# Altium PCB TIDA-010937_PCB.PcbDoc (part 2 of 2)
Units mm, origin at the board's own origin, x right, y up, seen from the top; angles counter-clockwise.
Board outline 43.5 x 86.34 mm, 4 copper layers (Top Layer, GND, PWR, Bottom Layer), stack 1.856 mm thick; 90 components, 44 nets, 203 pads, 101 vias.
Unrouted connection lines stored in the file: 1.
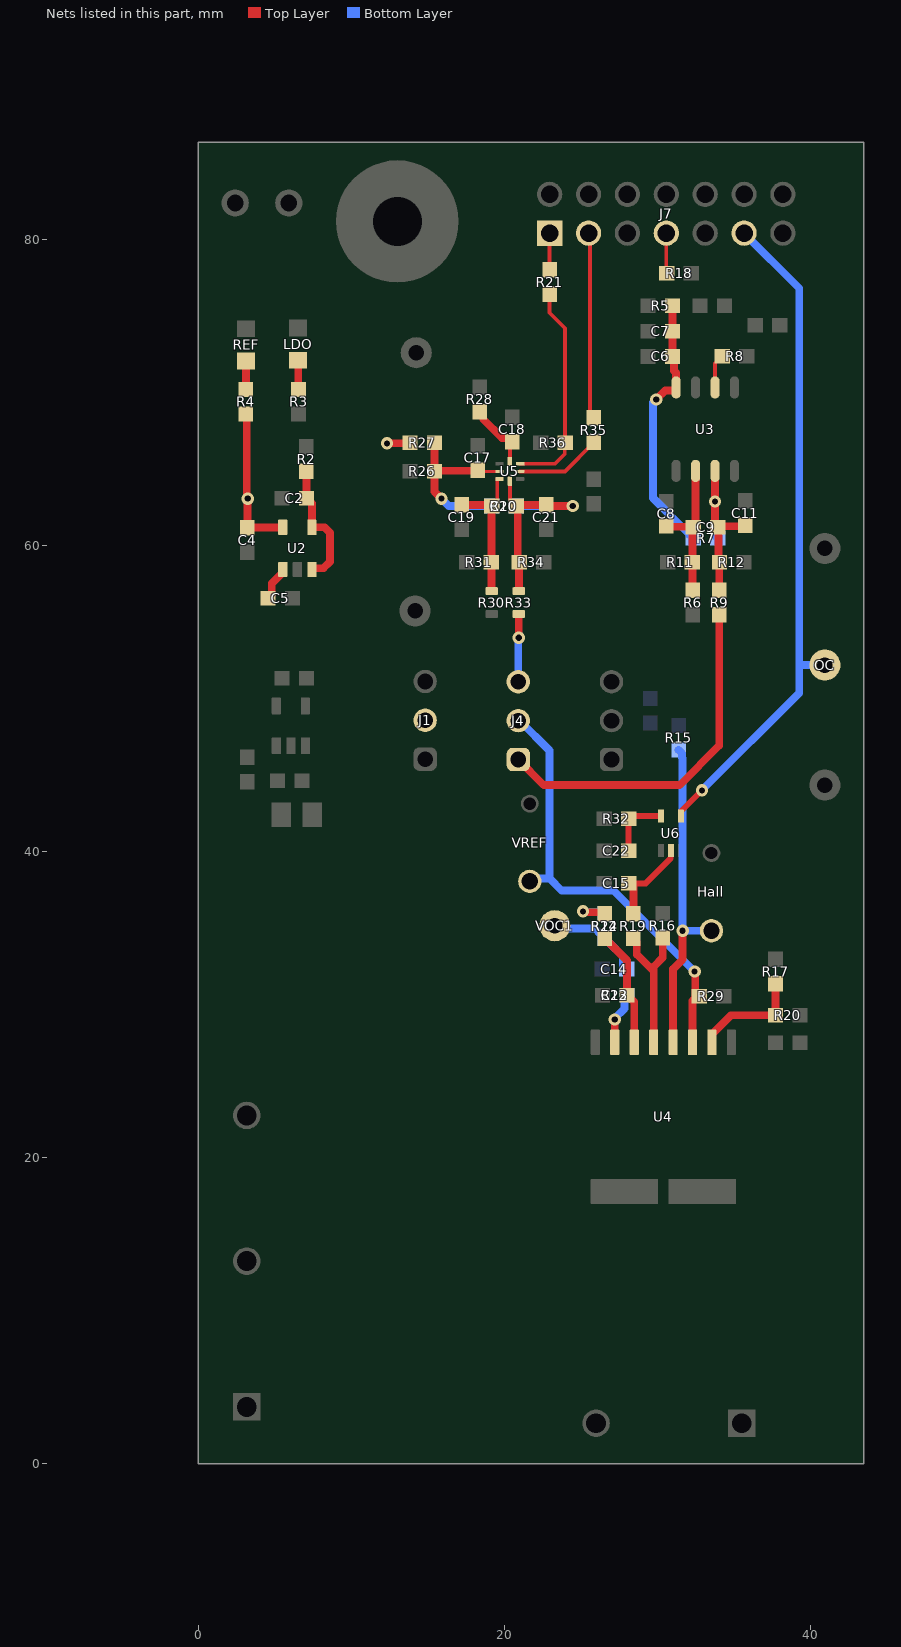
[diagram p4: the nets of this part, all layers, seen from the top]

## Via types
v1: diameter 0.8, hole 0.4, Top Layer to Bottom Layer, 101 vias

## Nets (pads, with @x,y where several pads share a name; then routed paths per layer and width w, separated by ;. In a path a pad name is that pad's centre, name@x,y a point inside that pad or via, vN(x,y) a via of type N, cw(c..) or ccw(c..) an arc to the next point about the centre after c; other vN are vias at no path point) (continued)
NetC2_1: C2.1 R2.2 U2.3 U2.4 | length 8.1
  Top Layer w0.508: C2.1@7.076,63.089 R2.2@7.076,64.836 ; C2.1@7.322,62.843 7.431,62.734 U2.4@7.431,61.177 8.258,61.177 8.614,60.82 8.614,58.934 8.185,58.505 7.477,58.505 7.431,58.459 U2.3@7.431,58.427
NetC8_2: C8.2 C9.1 R6.2 R11.2 U3.2 | length 9.4
  Top Layer w0.508: C8.2@30.572,61.26 30.612,61.22 32.191,61.22 C9.1@32.358,61.053 ; R6.2@32.319,57.064 32.302,57.08 32.302,58.874 R11.2@32.286,58.89 32.305,58.909 32.305,61.07 C9.1@32.324,61.089 ; C9.1@32.5,61.424 U3.2@32.5,64.864
NetC9_2: C9.2 C11.1 R7.1 R9.2 R12.2 U3.3 | length 12.1
  Top Layer w0.508: U3.3@33.77,64.864 v1(33.77,62.86) 33.77,61.368 C9.2@33.958,61.18 ; C9.2@33.924,61.089 33.991,61.021 33.991,58.958 R12.2@34.059,58.89 34.054,58.885 34.054,57.069 R9.2@34.049,57.064 ; C9.2@34.02,61.242 35.689,61.242 C11.1@35.751,61.304
  Bottom Layer w0.508: v1(33.77,62.86) 33.77,60.643 R7.1@33.958,60.455
NetC12_1: C12.1 R14.1 U4.8 | length 7.6
  Top Layer w0.508: R14.1@26.567,34.33 26.567,34.305 26.788,34.084 26.813,34.084 28.021,32.875 C12.1@28.021,30.606 28.046,30.606 28.491,30.161 U4.8@28.491,27.534
NetC15_1: C15.1 R19.2 U6.2 | length 6.1
  Top Layer w0.381: C15.1@28.124,37.918 28.149,37.918 29.245,37.918 30.882,39.555 30.882,40.053 U6.2@30.891,40.062
  Top Layer w0.508: C15.1@28.149,37.918 28.439,37.629 R19.2@28.439,35.93
NetC18_2: C18.2 R28.1 U5.4 | length 4.4
  Top Layer w0.254: U5.4@20.365,65.484 20.365,66.587 C18.2@20.524,66.745
  Top Layer w0.508: R28.1@18.413,68.737 18.634,68.516 18.634,68.241 19.859,67.016 20.303,67.016 20.37,66.95 C18.2@20.37,66.78
NetC19_2: C19.2 C20.1 R30.1 R31.2 U5.7 | length 9.6
  Top Layer w0.254: C20.1@19.183,62.57 19.208,62.57 19.232,62.594 19.542,62.904 19.542,64.332 19.544,64.334 U5.7@19.69,64.334
  Top Layer w0.508: C19.2@17.274,62.68 17.311,62.642 19.184,62.642 19.222,62.605 19.232,62.594 C20.1@19.256,62.57 ; R30.1@19.179,57.064 19.164,57.079 19.164,58.873 R31.2@19.148,58.889 19.166,58.906 19.166,62.552 C20.1@19.183,62.57 ; R31.2@19.265,58.908 R31.2@19.268,58.905
NetC20_2: C20.2 C21.1 R10.1 R33.1 R34.2 U5.8 | length 15.2
  Top Layer w0.254: U5.8@20.365,64.184 20.365,62.963 20.686,62.642 C20.2@20.859,62.642
  Top Layer w0.508: R33.1@20.948,57.064 20.964,57.08 20.964,58.874 R34.2@20.98,58.89 20.882,58.989 R34.2@20.882,59.107 ; R34.2@21.1,58.907 21.083,58.907 R34.2@20.882,59.107 ; C21.1@22.752,62.645 C21.1@22.754,62.643 ; v1(24.478,62.57) 22.827,62.57 C21.1@22.754,62.643 ; R34.2@20.882,59.107 20.882,62.545 20.822,62.605 20.859,62.642 22.753,62.642 C21.1@22.754,62.643
  Bottom Layer w0.508: R10.1@20.783,62.57 v1(24.478,62.57)
NetC22_1: C22.1 R32.1 U6.5 | length 4.3
  Top Layer w0.381: C22.1@28.124,40.044 R32.1@28.124,42.14 28.296,42.312 U6.5@30.241,42.312
NetJ7_1: J7.1 R21.2 | length 2.6
  Top Layer w0.254: R21.2@22.968,77.788 J7.1@22.968,80.405
NetJ7_7: J7.7 R18.2 | length 2.6
  Top Layer w0.254: J7.7@30.588,80.397 30.588,77.812 R18.2@30.62,77.779
NetLDO_2: LDO.2 R3.1 | length 2
  Top Layer w0.508: LDO.2@6.527,72.095 6.543,72.079 6.543,70.242 6.601,70.184 R3.1@6.601,70.209
NetR4_1: R4.1 REF.2 | length 1.9
  Top Layer w0.508: R4.1@3.11,70.184 3.12,70.194 3.12,72.044 REF.2@3.131,72.054
NetR8_1: R8.1 U3.6 | length 2.2
  Top Layer w0.254: U3.6@33.77,70.314 33.77,71.9 34.221,72.35 R8.1@34.246,72.35
NetR16_1: R16.1 R19.1 U4.7 | length 9.8
  Top Layer w0.508: R19.1@28.439,34.33 28.66,34.109 28.66,33.274 29.761,32.172 ; U4.7@29.761,27.534 29.761,32.172 ; R16.1@30.354,34.348 30.354,33.069 29.761,32.476 29.761,32.172
NetR17_1: R17.1 R20.1 U4.4 | length 7.2
  Top Layer w0.508: U4.4@33.571,27.534 33.571,28.059 34.819,29.306 R20.1@37.723,29.306 R17.1@37.723,31.356
NetR35_2: R35.2 U5.2 | length 5.6
  Top Layer w0.254: U5.2@21.04,64.834 23.969,64.834 25.84,66.705 R35.2@25.84,66.73
OC_Blank: J7.11 OC.1 U6.4 | length 44.5
  Top Layer w0.381: U6.4@31.541,42.312 31.551,42.322 31.551,42.629 v1(32.915,43.993)
  Bottom Layer w0.508: v1(32.915,43.993) 39.273,50.351 39.273,52.18 ; J7.11@35.668,80.397 39.273,76.792 39.273,52.18 ; OC.1@40.947,52.18 39.273,52.18
REF_ADS: J4.3 R33.2 | length 4.4
  Top Layer w0.508: v1(20.948,53.96) R33.2@20.948,55.439
  Bottom Layer w0.508: J4.3@20.919,51.09 20.919,53.93 v1(20.948,53.96)
REF_AMC: J4.1 R9.1 | length 23.4
  Top Layer w0.508: J4.1@20.919,46.01 22.591,44.338 31.458,44.338 34.049,46.929 R9.1@34.049,55.464
SCLK: R21.1 R36.2 U5.3 | length 14.1
  Top Layer w0.254: U5.3@21.04,65.334 23.308,65.334 23.956,65.982 23.956,66.341 24.304,66.689 R36.2@24.316,66.689 ; R21.1@22.968,76.322 22.968,75.193 23.977,74.184 R36.2@23.977,66.689
SDO: J7.3 R35.1 | length 12.6
  Top Layer w0.254: J7.3@24.963,80.564 25.601,79.925 25.601,68.568 R35.1@25.84,68.33
V_Hall: J1.2 R14.2 R22.1 | length 3
  Top Layer w0.508: v1(25.146,36.089) 25.202,36.033 26.463,36.033 R14.2@26.567,35.93
  Bottom Layer w0.508: v1(25.146,36.089) 25.202,36.033 26.463,36.033 R22.1@26.567,35.93
VBIAS: C5.1 U2.1 | length 2.3
  Top Layer w0.508: C5.1@4.563,56.529 4.588,56.529 4.809,56.75 4.809,57.504 5.531,58.227 U2.1@5.531,58.427
VDD_ADS: C17.2 R10.2 R26.2 R27.2 U5.6 | length 11.4
  Top Layer w0.152: C17.2@18.243,64.871 C17.2@18.28,64.834
  Top Layer w0.2: C17.2@18.28,64.834 U5.6@19.69,64.834
  Top Layer w0.508: R27.2@15.476,66.546 15.439,66.509 R26.2@15.439,64.845 15.439,63.512 v1(15.899,63.052) ; R26.2@15.514,64.871 C17.2@18.243,64.871
  Bottom Layer w0.508: v1(15.899,63.052) 16.381,62.57 R10.2@19.183,62.57
VDD_AMC: C6.2 C7.1 R5.2 R7.2 U3.8 | length 17.4
  Top Layer w0.508: v1(29.93,69.537) 30.513,70.121 31.188,70.121 31.213,70.146 U3.8@31.213,70.314 ; R5.2@30.993,75.655 C7.1@30.993,73.992 C6.2@30.993,72.339 31.096,72.236 31.096,71.406 31.23,71.272 U3.8@31.23,70.314
  Bottom Layer w0.508: v1(29.93,69.537) 29.718,69.325 29.718,63.096 32.112,60.701 32.112,60.676 32.333,60.455 R7.2@32.358,60.455
VOC1: C14.1 R22.2 R23.1 U4.9 VOC1.1 | length 11.1
  Top Layer w0.508: U4.9@27.175,27.58 U4.9@27.221,27.534 v1(27.221,29.021)
  Bottom Layer w0.508: VOC1.1@23.304,35.148 23.476,34.976 25.921,34.976 26.321,34.576 26.346,34.576 26.567,34.355 R22.2@26.567,34.33 ; R22.2@26.813,34.084 27.768,33.129 27.768,32.541 27.989,32.32 C14.1@27.996,32.32 ; v1(27.221,29.021) 27.221,29.1 27.856,29.735 27.856,30.44 R23.1@28.021,30.606 C14.1@28.021,32.32
Vout: Hall.1 R15.1 U4.6 | length 21.3
  Top Layer w0.508: U4.6@31.031,27.534 31.031,32.32 31.654,32.944 v1(31.654,34.819)
  Bottom Layer w0.508: R15.1@31.391,46.627 31.612,46.406 31.612,46.126 31.654,46.084 v1(31.654,34.819) Hall.1@33.539,34.819
VREF: J4.2 R29.2 U4.5 VREF.1 | length 29.3
  Top Layer w0.508: U4.5@32.301,27.534 32.301,30.237 R29.2@32.522,30.458 ; v1(32.44,32.151) 32.482,32.109 32.482,30.549 R29.2@32.524,30.507
  Bottom Layer w0.508: J4.2@20.919,48.55 21.006,48.55 22.957,46.6 22.957,38.24 ; VREF.1@21.673,38.045 21.867,38.24 22.957,38.24 ; v1(32.44,32.151) 27.148,37.443 23.753,37.443 22.957,38.24
VREF_3V3: C4.1 R4.2 R27.1 U2.5 | length 11.3
  Top Layer w0.508: R4.2@3.11,68.584 3.183,68.511 3.183,63.108 v1(3.239,63.052) 3.231,63.044 C4.1@3.231,61.153 ; C4.1@3.223,61.145 C4.1@3.231,61.153 ; U2.5@5.531,61.177 5.516,61.161 3.239,61.161 C4.1@3.231,61.153 ; v1@12.349,66.678 13.827,66.678 R27.1@13.839,66.689 R27.1@13.811,66.717
  other v1: 12.337,66.666
pads on no net: H1.1 J5.2 LBL1.0 U1.4 U3.4 U4.10 U6.1

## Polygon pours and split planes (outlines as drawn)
IN- on PWR "PWR_IN-_P060" (solid, pour order 60): 37.902,16.967 37.902,1.651 30.72,1.651 30.72,16.967
IN+ on PWR "PWR_IN+_P057" (solid, remove dead copper, pour order 57): 30.063,16.967 30.063,1.651 22.882,1.651 22.882,16.967
+5V on PWR "PWR_+5V_P043" (solid, remove dead copper, pour order 43): 0,86.341 11.328,86.341 11.328,33.399 9.026,33.392 0,33.392
V_Hall on PWR "PWR_V_HALL_P042" (solid, remove dead copper, pour order 42): 11.34,50.091 18.587,50.091 18.587,47.098 34.004,31.681 43.5,31.681 43.5,26.459 43.456,26.415 43.412,26.459 25.202,26.459 25.202,33.392 11.243,33.392
LDO_3V3 on PWR "PWR_LDO_3V3_P045" (solid, remove dead copper, pour order 45): 11.34,50.091 11.328,50.103 11.328,86.341 43.5,86.341 43.5,31.681 34.004,31.681 18.587,47.098 18.587,50.091
+5V on PWR "PWR_+5V_P044" (solid, remove dead copper, pour order 44): 10.847,46.874 16.022,46.874 16.1,46.797 16.1,44.979 10.897,44.979 10.847,45.028
GND on Top Layer "TOP_LAYER_GND_P047" (solid, remove dead copper, pour order 47): 0,86.341 43.5,86.341 43.5,26.459 25.202,26.459 25.202,33.392 0,33.392
IN- on Top Layer "TOP_LAYER_IN-_P020" (solid, pour order 20): 37.902,18.603 37.902,1.651 30.72,1.651 30.72,18.603
IN1 on Top Layer "TOP_LAYER_IN1_P055" (solid, pour order 55): 0,25.654 10.636,25.654 10.795,25.495 10.795,20.211 0.051,20.211 0,20.262
IN1 on Top Layer "TOP_LAYER_IN1_P054" (solid, pour order 54): 0,7.043 10.636,7.043 10.795,6.883 10.795,1.6 0.051,1.6 0,1.651
IN1 on Top Layer "TOP_LAYER_IN1_P053" (solid, pour order 53): 9.722,1.651 17.78,1.651 17.813,22.659 14.975,25.654 9.715,25.654
IN+ on Top Layer "TOP_LAYER_IN+_P016" (solid, remove dead copper, pour order 16): 30.063,18.603 30.063,1.651 22.882,1.651 22.882,18.603
LDO_3V3 on Top Layer "TOP_LAYER_LDO_3V3_P031" (solid, remove dead copper, pour order 31): 4.92,50.833 7.836,50.833 7.836,54.831 7.733,54.934 4.889,54.934 4.762,54.807 4.762,51.107
IN- on Bottom Layer "BOTTOM_LAYER_IN-_P061" (solid, pour order 61): 37.902,16.967 37.902,1.651 30.72,1.651 30.72,16.967
IN+ on Bottom Layer "BOTTOM_LAYER_IN+_P058" (solid, remove dead copper, pour order 58): 30.063,16.967 30.063,1.651 22.882,1.651 22.882,16.967
LDO_3V3 on Bottom Layer "BOTTOM_LAYER_LDO_3V3_P030" (solid, remove dead copper, pour order 30): 4.762,54.807 4.889,54.934 10.979,54.934 10.979,57.45 16.798,57.45 16.798,50.182 16.713,50.096 4.982,50.096 4.762,50.316
VREF_3V3 on Bottom Layer "BOTTOM_LAYER_VREF_3V3_P006" (solid, remove dead copper, pour order 6): 2.379,67.463 2.379,60.295 14.471,60.295 14.471,67.463
IN- on GND "GND_IN-_P059" (solid, pour order 59): 37.902,16.967 37.902,1.651 30.72,1.651 30.72,16.967
IN+ on GND "GND_IN+_P056" (solid, remove dead copper, pour order 56): 30.063,16.967 30.063,1.651 22.882,1.651 22.882,16.967
GND on GND "GND_GND_P046" (solid, pour order 46): 0,86.341 43.5,86.341 43.5,26.547 43.412,26.459 25.202,26.459 25.202,33.392 0,33.392

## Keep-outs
Keep-Out Layer:
  text ".Layer_Name" at 14.656,-21.806 h1.02

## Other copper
Top Layer:
  pour cut-out: 37.902,16.967 35.136,16.967 35.136,18.603 37.902,18.603
  pour cut-out: 25.647,16.967 22.882,16.967 22.882,18.603 25.647,18.603
  text ".Layer_Name" at 14.656,-21.806 h1.02
GND:
  pour cut-out: 37.902,16.967 35.136,16.967 35.136,18.603 37.902,18.603
  pour cut-out: 25.647,16.967 22.882,16.967 22.882,18.603 25.647,18.603
PWR:
  pour cut-out: 37.902,16.967 35.136,16.967 35.136,18.603 37.902,18.603
  pour cut-out: 25.647,16.967 22.882,16.967 22.882,18.603 25.647,18.603
Bottom Layer:
  pour cut-out: 37.902,16.967 35.136,16.967 35.136,18.603 37.902,18.603
  pour cut-out: 25.647,16.967 22.882,16.967 22.882,18.603 25.647,18.603
  text ".Layer_Name" at 14.656,-21.806 h1.02

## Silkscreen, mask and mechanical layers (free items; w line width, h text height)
Top Overlay:
  lines w0.508: 0.449,33.392 25.202,33.392 25.202,26.455 43.456,26.415
  text "+5V" at 0.676,76.842 h1.02
  text "GND" at 5.111,76.842 h1.02
  text "1:SCLK / 3:SDO / 5:CS / 7:CLK / 9:DOUT / 11:OC / 13:FAULT" at 37.791,65.156 h1.02
  text "3V3" at 16.475,50.775 h1.02
  text "ADS" at 23.093,50.786 h1.02
  text "5V" at 16.493,45.627 h1.02
  text "AMC" at 23.023,45.602 h1.02
  text "TIDA-010937-E1" at 3.113,29.905 h2.54
  text "850V  / MAX" at 18.432,20.211 h1.52
  text "66A  / MAX" at 38.156,20.218 h1.52
  text ".Layer_Name" at 14.656,-21.806 h1.02
Bottom Overlay:
  text "IN+" at 22.034,11.182 h1.52 r180
  text "IN-" at 42.599,11.182 h1.52 r180
  text ".Layer_Name" at 14.656,-21.806 h1.02
Top Paste:
  text ".Layer_Name" at 14.656,-21.806 h1.02
Bottom Paste:
  text ".Layer_Name" at 14.656,-21.806 h1.02
Top Solder:
  text ".Layer_Name" at 14.656,-21.806 h1.02
  text ".Layer_Name" at 14.656,-21.806 h1.02
Bottom Solder:
  text ".Layer_Name" at 14.656,-21.806 h1.02
Drill Guide:
  text ".Layer_Name" at 14.656,-21.806 h1.02
M1 Board Outline:
  the board outline again, w0.254
  text ".Layer_Name" at 14.656,-21.806 h1.02
M2 Board Dimensions:
  rectangle: 0,-6.985 3.175,-3.81
  rectangle: 3.175,-10.16 12.7,-6.985
  lines w0.178: 0,-6.985 25.4,-6.985 ; 3.175,-10.16 3.175,-3.81 ; 6.35,-10.16 6.35,-3.81 ; 12.7,-10.16 12.7,-3.81 ; 19.05,-10.16 19.05,-3.81 ; 0,-10.16 25.4,-10.16 25.4,-3.81 0,-3.81 0,-10.16
  text ".Layer_Name" at 14.656,-21.806 h1.02
M3 3D STEP Top:
  text ".Layer_Name" at 14.656,-21.806 h1.02
M4 3D STEP Bottom:
  text ".Layer_Name" at 14.656,-21.806 h1.02
M5 Assembly Top:
  lines w0.254: -7.417,-23.626 160.223,-23.626 ; -7.417,-18.462 160.274,-18.462 ; -7.417,-13.297 -7.417,-28.791 94.31,-28.791 160.274,-28.791 160.274,-13.297 -7.404,-13.297 -7.404,-28.791 32.614,-28.791 ; 55.194,-28.791 55.194,-13.297 ; 87.376,-18.462 87.376,-13.297 ; 108.712,-18.462 108.712,-13.297 ; 124.511,-28.956 124.511,-23.804
  text "COMPONENTS MARKED 'DNP' SHOULD NOT BE POPULATED." at 29.299,-8.09 h1.02
  text "ASSEMBLY VARIANT:" at 29.286,-11.024 h1.02
  text ".VariantName" at 55.601,-11.024 h1.02
  text "PCB VIEWED FROM TOP SIDE" at -5.804,-16.654 h1.02
  text "BOARD #:" at 57.099,-16.654 h1.02
  text ".PRJ_Number" at 70.955,-16.654 h1.02
  text "REV:" at 92.405,-16.654 h1.02
  text ".PCB_Rev" at 99.809,-16.654 h1.02
  text "SVN REV:" at 113.69,-16.654 h1.02
  text ".VersionControl_RevNumber" at 126.543,-16.654 h1.02
  text "TID #:" at 57.099,-21.819 h1.02
  text ".TID" at 70.955,-21.819 h1.02
  text "PLOT NAME =" at -5.804,-27.034 h1.02
  text ".plot_File_Name" at 14.656,-27.034 h1.02
  text "GENERATED    :" at 57.15,-27.034 h1.02
  text ".Print_Date" at 79.235,-27.034 h1.02
  text ".Print_Time" at 97.752,-27.034 h1.02
  text "TEXAS INSTRUMENTS" at 129.87,-27.034 h1.02
M6 Assembly Bottom:
  lines w0.254: -7.429,-18.474 160.261,-18.474 ; -7.379,-23.639 160.261,-23.639 ; 28.334,-28.969 28.334,-23.817 ; 44.133,-18.474 44.133,-13.31 ; 65.468,-18.474 65.468,-13.31 ; 97.65,-28.804 97.65,-13.31 ; 120.231,-28.804 160.249,-28.804 160.249,-13.31 -7.429,-13.31 -7.429,-28.804 58.534,-28.804 160.261,-28.804 160.261,-13.31
  text "COMPONENTS MARKED 'DNP' SHOULD NOT BE POPULATED." at 154.991,-8.077 h1.02
  text ".VariantName" at 128.473,-11.024 h1.02
  text "ASSEMBLY VARIANT:" at 154.864,-11.024 h1.02
  text ".VersionControl_RevNumber" at 26.302,-16.667 h1.02
  text "SVN REV:" at 39.154,-16.667 h1.02
  text ".PCB_Rev" at 53.035,-16.667 h1.02
  text "REV:" at 60.439,-16.667 h1.02
  text ".PRJ_Number" at 81.89,-16.667 h1.02
  text "BOARD #:" at 95.745,-16.667 h1.02
  text "PCB VIEWED FROM BOTTOM SIDE" at 158.648,-16.667 h1.02
  text ".TID" at 81.89,-21.831 h1.02
  text "TID #:" at 95.745,-21.831 h1.02
  text "TEXAS INSTRUMENTS" at 22.974,-27.047 h1.02
  text ".Print_Time" at 55.093,-27.047 h1.02
  text ".Print_Date" at 73.609,-27.047 h1.02
  text "GENERATED    :" at 95.694,-27.047 h1.02
  text ".plot_File_Name" at 138.189,-27.047 h1.02
  text "PLOT NAME =" at 158.648,-27.047 h1.02
M9 Title Sheet:
  drawing of 57 lines, arcs and shapes, not listed
  text "1" at 18.792,204.127 h1.78
  text "2" at 82.182,204.127 h1.78
  text "3" at 145.411,204.127 h1.78
  text "4" at 209.08,204.127 h1.78
  text "5" at 272.555,204.127 h1.78
  text "6" at 336.182,204.127 h1.78
  text "A" at -10.579,175.095 h1.78
  text "A" at 365.341,175.095 h1.78
  text "B" at -10.579,114.643 h1.78
  text "B" at 365.341,114.643 h1.78
  text "C" at -10.579,54.318 h1.78
  text "C" at 365.341,54.318 h1.78
  text "PROJECT TITLE:" at 288.125,7.048 h1.14
  text ".PRJ_Title" at 289.395,3.662 h1.78
  text "DESIGNED FOR:" at 288.125,-0.597 h1.14
  text ".PRJ_Customer" at 289.395,-4.153 h1.78
  text "D" at -10.579,-5.88 h1.78
  text "D" at 365.341,-5.88 h1.78
  text "FILE NAME:" at 288.125,-8.217 h1.14
  text ".PCB_File_Name_No_Path" at 289.395,-11.265 h1.78
  text "Texas Instruments (TI) and/or its licensors do not warrant the accuracy or completeness of this specification" at 161.9,-15.376 h1.14
  text "ENGINEER:" at 288.125,-15.583 h1.14
  text "LAYOUT BY:" at 326.352,-15.583 h1.14
  text "or any information contained therein. TI and/or its licensors do not warrant that this design will meet" at 160.757,-18.237 h1.14
  text ".PRJ_Engineer" at 289.395,-19.52 h1.78
  text ".PCB_Layout" at 327.635,-19.52 h1.78
  text "the specifications, will be suitable for your application or fit for any particular purpose, or will operate in" at 160.757,-21.099 h1.14
  text ".Layer_Name" at 14.656,-21.806 h1.02
  text "ALTIUM DESIGNER VERSION:" at 326.352,-23.457 h1.14
  text "an implementation. TI and/or its licensors do not warrant that the design is production worthy. You should" at 160.757,-23.961 h1.14
  text "completely validate and test your design implementation to confirm the system functionality for your application." at 161.9,-26.822 h1.14
  text ".print_Scale" at 289.395,-26.843 h1.78
  text ".Application_BuildNumber" at 327.635,-26.843 h1.78
  text "1" at 18.792,-32.093 h1.78
  text "2" at 82.182,-32.093 h1.78
  text "3" at 145.411,-32.093 h1.78
  text "4" at 209.08,-32.093 h1.78
  text "5" at 272.555,-32.093 h1.78
  text "6" at 336.182,-32.093 h1.78
M10 Fab Notes:
  drawing of 189 lines, arcs and shapes, not listed
  text "DESIGN INFORMATION" at 314.503,161.447 h1.02
  text "MIN. TRACK WIDTH:" at 298.131,158.091 h1.02
  text "8" at 325.976,158.091 h1.02
  text "MIL" at 329.907,158.091 h1.02
  text "7.874" at 321.75,155 h1.02
  text "MIN. CLEARANCE:" at 298.131,154.938 h1.02
  text "MIL" at 329.907,154.938 h1.02
  text "MIN. VIA PAD SIZE:" at 298.131,151.785 h1.02
  text "24" at 325.214,151.785 h1.02
  text "MIL" at 329.907,151.785 h1.02
  text "0.05mm (2MIL)" at 315.784,148.486 h1.02
  text "MINIMUM ANNULAR RING" at 289.769,148.277 h1.02
  text "EXTERNAL" at 333.768,148.277 h1.02
  text "PER" at 294.849,145.48 h1.02
  text "IPC-D-275 CLASS 2 LEVEL C" at 300.437,145.48 h1.02
  text "MIL, HOLES" at 338.238,142.928 h1.02
  text "+/-" at 328.27,142.709 h1.02
  text "+/-" at 349.961,142.709 h1.02
  text "REGISTRATION TOLERANCES:" at 289.769,142.682 h1.02
  text "METAL" at 320.243,142.682 h1.02
  text "5" at 334.879,142.683 h1.02
  text "3" at 356.037,142.683 h1.02
  text "MIL" at 358.99,142.682 h1.02
  text "HOLE SIZE TOLERANCE (UNLESS OTHERWISE SPECIFIED):" at 289.769,140.185 h1.02
  text "+/-" at 349.961,140.112 h1.02
  text "3" at 356.037,140.085 h1.02
  text "MIL" at 358.99,140.085 h1.02
  text "MATERIAL:" at 287.87,136.589 h1.02
  text "FR-4 High Tg" at 312.926,133.324 h1.02
  text "X" at 309.257,133.122 h1.02
  text "FR-4" at 298.563,133.007 h1.02
  text "OTHER" at 336.358,133.007 h1.02
  text "62 MIL (1.6mm) +/-10%" at 306.694,129.374 h1.02
  text "X" at 303.643,129.312 h1.02
  text "THICKNESS:" at 289.769,129.165 h1.02
  text "OTHER" at 339.33,129.165 h1.02
  text "TOLERANCE:" at 289.769,125.652 h1.02
  text "X" at 311.314,125.652 h1.02
  text "ANSI IPC-6012 TYPE 3 CLASS 2" at 315.836,125.652 h1.02
  text "OTHER +/-" at 315.835,121.989 h1.02
  text "BOW & TWIST:" at 289.769,118.302 h1.02
  text "X" at 311.314,118.302 h1.02
  text "ANSI IPC-6012 TYPE 3 CLASS 2" at 315.836,118.302 h1.02
  text "OTHER +/-" at 315.835,114.576 h1.02
  text "DRILLING:" at 287.87,111.258 h1.02
  text "NC_DRILL FILES" at 332.599,108.586 h1.02
  text "REFERENCE:" at 289.769,108.486 h1.02
  text "X" at 306.463,108.484 h1.02
  text "AS SHOWN" at 310.984,108.486 h1.02
  text "X" at 329.348,108.486 h1.02
  text "OTHER" at 340.168,104.873 h1.02
  text "PTH COPPER THICKNESS:" at 289.761,104.783 h1.02
  text "X" at 318.697,104.783 h1.02
  text "20-30 um" at 321.948,104.783 h1.02
  text "BOARD FINISH:" at 287.87,101.034 h1.02
  text "SILKSCREEN:" at 291.812,98.237 h1.02
  text "X" at 316.14,98.237 h1.02
  text "TOP" at 319.112,98.237 h1.02
  text "X" at 329.094,98.237 h1.02
  text "BOTTOM" at 332.091,98.237 h1.02
  text "SILKSCREEN COLOR:" at 291.812,94.295 h1.02
  text "X" at 316.115,94.295 h1.02
  text "WHITE" at 319.112,94.295 h1.02
  text "OTHER" at 332.091,94.295 h1.02
  text "X" at 319.442,90.652 h1.02
  text "GREEN" at 322.439,90.652 h1.02
  text "OTHER" at 338.136,90.652 h1.02
  text "SOLDER RESIST COLOR:" at 291.812,90.477 h1.02
  text "X" at 319.442,86.734 h1.02
  text "MATTE" at 322.439,86.734 h1.02
  text "SEMI-GLOSS" at 338.125,86.717 h1.02
  text "IMMERSION GOLD (ENIG)" at 314.819,82.345 h1.02
  text "ENEPIG" at 348.793,82.162 h1.02
  text "SURFACE FINISH:" at 287.87,82.136 h1.02
  text "X" at 310.298,82.136 h1.02
  text "IMM. TIN/SILVER OR EQUIV" at 296.24,78.649 h1.02
  text "OTHER" at 332.599,78.549 h1.02
  text "ARRAY/PANEL:" at 287.87,74.602 h1.02
  text "CUT AND TRIM PER M1 BOARD OUTLINE" at 314.819,74.393 h1.02
  text "N.C. ROUTE" at 314.819,70.94 h1.02
  text "X" at 332.295,70.94 h1.02
  text "V. SCORE" at 336.816,70.94 h1.02
  text "CERTIFICATION:" at 287.87,67.66 h1.02
  text "MATERIALS AND WORKMANSHIP FOR ALL PCBS" at 306.285,67.66 h1.02
  text "TO MEET OR EXCEED THE REQUIREMENTS OF:" at 306.285,65.271 h1.02
  text "X" at 297.078,62.003 h1.02
  text "ANSI IPC-A-600F CLASS ->" at 300.329,62.003 h1.02
  text "X" at 342.188,62.003 h1.02
  text "2" at 344.982,62.003 h1.02
  text "1" at 336.981,61.965 h1.02
  text "3" at 353.973,61.965 h1.02
  text "X" at 317.702,58.252 h1.02
  text "RoHS" at 320.953,58.252 h1.02
  text "OTHER" at 337.321,58.252 h1.02
  text "PER ORDER" at 347.407,58.252 h1.02
  text "ALL BOARDS MUST MEET OR EXCEED UL94-V0 REQUIREMENTS." at 288.569,54.345 h1.02
  text "PCB MUST BEAR THE UL94V-0 UL REGISTERED MATERIAL ID NUMBER" at 288.569,51.397 h1.02
  text "ADDITIONAL REQUIREMENTS:" at 287.87,47.094 h1.02
  text "MICROSECTION:" at 289.769,44.373 h1.02
  text "YES" at 312.775,44.373 h1.02
  text "REQUIRED" at 334.657,40.707 h1.02
  text "BARE BOARD ELEC. TEST:" at 289.769,40.634 h1.02
  text "NONE" at 322.935,40.634 h1.02
  text "X" at 331.66,40.634 h1.02
  text "PER ORDER" at 349.693,40.634 h1.02
  text "XX MIL VIAS REQUIRE NON-CONDUCTIVE FILL AND PLANARIZE" at 294.04,35.428 h1.5
  text "XX MIL VIAS REQUIRE CONDUCTIVE FILL AND PLANARIZE" at 294.243,32.787 h1.02
  text "OUTER XX MIL TRACES REQUIRE 50 OHM SINGLE-ENDED IMPEDANCE" at 294.218,28.637 h1.47
  text "LAYER 2 & 3 (INNER LAYERS) XX MIL WIDE, XX MIL SPACE / TRACES REQUIRE 100 OHM DIFFERENTIAL IMPEDANCE" at 294.015,22.65 h1.02
  text ".Layer_Name" at 14.656,-21.806 h1.02
M11 Gerber Information:
  lines w0.254: -7.417,-23.626 160.223,-23.626 ; -7.417,-18.462 160.274,-18.462 ; -7.417,-13.297 -7.417,-28.791 94.31,-28.791 160.274,-28.791 160.274,-13.297 -7.404,-13.297 -7.404,-28.791 32.614,-28.791 ; 55.194,-28.791 55.194,-13.297 ; 87.376,-18.462 87.376,-13.297 ; 108.712,-18.462 108.712,-13.297 ; 124.511,-28.956 124.511,-23.804
  text "ALL ARTWORK VIEWED FROM TOP SIDE" at -5.804,-16.654 h1.02
  text "BOARD #:" at 57.099,-16.654 h1.02
  text ".PRJ_Number" at 70.955,-16.654 h1.02
  text "REV:" at 92.405,-16.654 h1.02
  text ".PCB_Rev" at 99.809,-16.654 h1.02
  text "SVN REV:" at 113.69,-16.654 h1.02
  text ".VersionControl_RevNumber" at 126.543,-16.654 h1.02
  text "LAYER NAME =" at -5.804,-21.806 h1.02
  text "TID #:" at 57.099,-21.819 h1.02
  text ".TID" at 70.955,-21.819 h1.02
  text "PLOT NAME =" at -5.804,-27.034 h1.02
  text ".plot_File_Name" at 14.656,-27.034 h1.02
  text "GENERATED    :" at 57.15,-27.034 h1.02
  text ".Print_Date" at 79.235,-27.034 h1.02
  text ".Print_Time" at 97.752,-27.034 h1.02
  text "TEXAS INSTRUMENTS" at 129.87,-27.034 h1.02
M12 Stackup:
  drawing of 196 lines, arcs and shapes, not listed
  text "Layer" at 248.59,200.96 h0.9
  text "Name" at 252.358,200.96 h0.9
  text "Material" at 259.646,200.96 h0.9
  text "Thickness" at 266.195,200.96 h0.9
  text "Constant" at 271.574,200.96 h0.9
  text "Board Layer Stack" at 276.552,200.96 h0.9
  text "Top Overlay" at 252.358,199.16 h0.9
  text "Top Solder" at 252.358,197.36 h0.9
  text "Solder Resist" at 259.646,197.36 h0.9
  text "0.40mil" at 266.195,197.36 h0.9
  text "3.5" at 271.574,197.36 h0.9
  text "1" at 248.59,195.56 h0.9
  text "Top Layer" at 252.358,195.56 h0.9
  text "2.76mil" at 266.194,195.56 h0.9
  text "Dielectric 1" at 252.358,193.76 h0.9
  text "PP-006" at 259.646,193.76 h0.9
  text "2.80mil" at 266.194,193.76 h0.9
  text "4.1" at 271.574,193.76 h0.9
  text "2" at 248.59,191.96 h0.9
  text "GND" at 252.358,191.96 h0.9
  text "CF-004" at 259.646,191.96 h0.9
  text "1.38mil" at 266.195,191.96 h0.9
  text "Dielectric1" at 252.358,190.16 h0.9
  text "FR-4 High Tg" at 259.646,190.16 h0.9
  text "59.20mil" at 266.195,190.16 h0.9
  text "4.8" at 271.574,190.16 h0.9
  text "3" at 248.59,188.36 h0.9
  text "PWR" at 252.358,188.36 h0.9
  text "CF-004" at 259.646,188.36 h0.9
  text "1.38mil" at 266.195,188.36 h0.9
  text "Dielectric 2" at 252.358,186.56 h0.9
  text "PP-006" at 259.646,186.56 h0.9
  text "2.80mil" at 266.194,186.56 h0.9
  text "4.1" at 271.574,186.56 h0.9
  text "4" at 248.59,184.76 h0.9
  text "Bottom Layer" at 252.358,184.76 h0.9
  text "2.76mil" at 266.194,184.76 h0.9
  text "Bottom Solder" at 252.358,182.96 h0.9
  text "Solder Resist" at 259.646,182.96 h0.9
  text "0.40mil" at 266.195,182.96 h0.9
  text "3.5" at 271.574,182.96 h0.9
  text "Bottom Overlay" at 252.358,181.16 h0.9
  text ".Layer_Name" at 14.656,-21.806 h1.02
M13 Component Bodies Top:
  text ".Layer_Name" at 14.656,-21.806 h1.02
M14 Component Bodies Bottom:
  text ".Layer_Name" at 14.656,-21.806 h1.02
M15 Courtyards Top:
  text ".Layer_Name" at 14.656,-21.806 h1.02
M16 Courtyards Bottom:
  text ".Layer_Name" at 14.656,-21.806 h1.02
Drill Drawing:
  circle w0.254: c135.463,81.749 r0.415
  lines w0.254: 135.049,70.138 135.049,70.345 135.256,70.552 135.049,70.76 135.049,70.967 135.256,70.967 135.463,70.76 135.671,70.967 135.878,70.967 135.878,70.76 135.671,70.552 135.878,70.345 135.878,70.138 135.671,70.138 135.463,70.345 135.256,70.138 135.049,70.138 ; 135.049,72.004 135.463,72.211 135.878,72.004 135.671,72.418 135.878,72.833 135.463,72.626 135.049,72.833 135.256,72.418 135.049,72.004 ; 135.049,73.87 135.878,73.87 135.878,74.699 135.049,74.699 135.049,73.87 ; 135.049,75.943 135.256,75.943 135.256,75.736 135.671,75.736 135.671,75.943 135.878,75.943 135.878,76.358 135.671,76.358 135.671,76.566 135.256,76.566 135.256,76.358 135.049,76.358 135.049,75.943 ; 135.049,78.432 135.878,78.432 135.463,77.602 135.049,78.432 ; 135.049,79.676 135.256,79.676 135.463,79.469 135.671,79.676 135.878,79.676 135.671,79.883 135.878,80.091 135.671,80.091 135.463,80.298 135.256,80.091 135.049,80.091 135.256,79.883 135.049,79.676 ; 135.049,83.201 135.878,83.201 135.878,84.03 135.049,84.03 135.049,83.201 ; 135.049,85.482 135.463,85.067 135.878,85.482 135.463,85.896 135.049,85.482 ; 135.215,74.036 135.712,74.036 135.712,74.533 135.215,74.533 135.215,74.036
  lines w0.305: 134.264,69.578 182.727,69.578 ; 134.264,86.373 182.727,86.373 ; 139.331,67.712 139.331,88.24 ; 144.309,67.712 144.309,88.24 ; 153.851,67.712 153.851,88.24 ; 157.737,67.712 157.737,88.24 ; 163.362,67.712 163.362,88.24 ; 174.235,67.712 174.235,88.24 ; 134.264,67.712 182.727,67.712 182.727,88.24 134.264,88.24 134.264,67.712
  text "Symbol" at 135.384,86.933 h1.08
  text "Quantity" at 139.891,86.933 h1.08
  text "Finished Hole Size" at 144.869,86.933 h1.08
  text "Plated" at 154.411,86.933 h1.08
  text "Hole Type" at 158.297,86.933 h1.08
  text "Drill Layer Pair" at 163.922,86.933 h1.08
  text "Hole Tolerance" at 174.795,86.933 h1.08
  text "101" at 139.891,85.067 h0.9
  text "15.75mil (0.400mm)" at 144.869,85.067 h0.9
  text "PTH" at 154.411,85.067 h0.9
  text "Round" at 158.297,85.067 h0.9
  text "Top Layer - Bottom Layer" at 163.922,85.067 h0.9
  text "2" at 139.891,83.201 h0.9
  text "32.00mil (0.813mm)" at 144.869,83.201 h0.9
  text "PTH" at 154.411,83.201 h0.9
  text "Round" at 158.297,83.201 h0.9
  text "Top Layer - Bottom Layer" at 163.922,83.201 h0.9
  text "6" at 139.891,81.335 h0.9
  text "40.00mil (1.016mm)" at 144.869,81.335 h0.9
  text "PTH" at 154.411,81.335 h0.9
  text "Round" at 158.297,81.335 h0.9
  text "Top Layer - Bottom Layer" at 163.922,81.335 h0.9
  text "9" at 139.891,79.469 h0.9
  text "40.16mil (1.020mm)" at 144.869,79.469 h0.9
  text "PTH" at 154.411,79.469 h0.9
  text "Round" at 158.297,79.469 h0.9
  text "Top Layer - Bottom Layer" at 163.922,79.469 h0.9
  text "2" at 139.891,77.602 h0.9
  text "42.00mil (1.067mm)" at 144.869,77.602 h0.9
  text "PTH" at 154.411,77.602 h0.9
  text "Round" at 158.297,77.602 h0.9
  text "Top Layer - Bottom Layer" at 163.922,77.602 h0.9
  text "2" at 139.891,75.736 h0.9
  text "43.31mil (1.100mm)" at 144.869,75.736 h0.9
  text "PTH" at 154.411,75.736 h0.9
  text "Round" at 158.297,75.736 h0.9
  text "Top Layer - Bottom Layer" at 163.922,75.736 h0.9
  text "14" at 139.891,73.87 h0.9
  text "44.88mil (1.140mm)" at 144.869,73.87 h0.9
  text "PTH" at 154.411,73.87 h0.9
  text "Round" at 158.297,73.87 h0.9
  text "Top Layer - Bottom Layer" at 163.922,73.87 h0.9
  text "5" at 139.891,72.004 h0.9
  text "51.18mil (1.300mm)" at 144.869,72.004 h0.9
  text "PTH" at 154.411,72.004 h0.9
  text "Round" at 158.297,72.004 h0.9
  text "Top Layer - Bottom Layer" at 163.922,72.004 h0.9
  text "+/-3.94mil" at 174.795,72.004 h0.9
  text "1" at 139.891,70.138 h0.9
  text "125.98mil (3.200mm)" at 144.869,70.138 h0.9
  text "PTH" at 154.411,70.138 h0.9
  text "Round" at 158.297,70.138 h0.9
  text "Top Layer - Bottom Layer" at 163.922,70.138 h0.9
  text "142 Total" at 139.891,68.271 h0.9
  text ".Layer_Name" at 14.656,-21.806 h1.02
M17 Embedded Cavity:
  text ".Layer_Name" at 14.656,-21.806 h1.02
M18 Embedded Assembly:
  text ".Layer_Name" at 14.656,-21.806 h1.02
M19 Embedded Keepout:
  text ".Layer_Name" at 14.656,-21.806 h1.02

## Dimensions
0,-10.16 to 25.4,-10.16 on M2 Board Dimensions
0,0 to 0,86.341 on M2 Board Dimensions
0,0 to 43.5,0 on M2 Board Dimensions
